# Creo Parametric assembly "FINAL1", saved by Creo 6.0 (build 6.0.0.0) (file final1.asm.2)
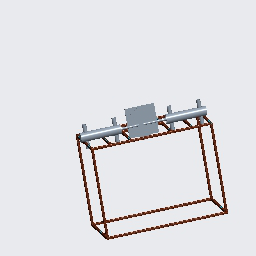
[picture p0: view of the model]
Units: millimeter Newton Second (mmNs); MM, TONNE, SECS

Created from: MMNS_ASM_DESIGN.ASM

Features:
  1. datum plane "ASM_RIGHT"
  2. datum plane "ASM_TOP"
  3. datum plane "ASM_FRONT"
  4. coordinate system
  5. component "ASM0001"
  6. component "CYLINDER"
  7. component "BAASE"
  8. component "CAM"
  9. component "CYLINDER"
  10. component "ASM0002"
  11. feature "Motor 1"
  12. component "CAP"
  13. component "CAP2"
  14. component "CAP"
  15. component "CAP2"

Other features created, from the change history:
  component "PRT0001.PRT"
  component "ASM0002.ASM" (2 times)
  feature "Motor 1" (2 times)
  feature "Motor 2" (2 times)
